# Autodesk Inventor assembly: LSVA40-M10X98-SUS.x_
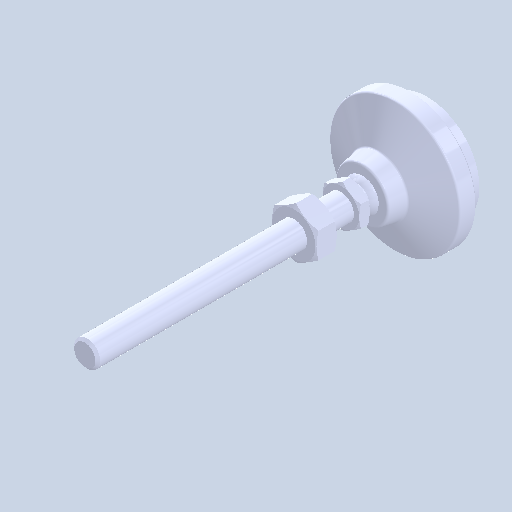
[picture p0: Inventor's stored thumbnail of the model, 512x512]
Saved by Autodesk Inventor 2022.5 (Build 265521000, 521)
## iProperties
Created: 2024-08
Part Number: LSVA40-M10X98-SUS.x_
Document SubType Name: Assembly
Designer: ImaoCorp
Author: ImaoCorp
Sending System: SOLIDWORKS 2022-2022290
MC: AMD64
MC_MODEL: Intel64 Family 6 Model 60 Stepping 3, GenuineIntel
OS: Windows_NT
FRU: Parasolid Version 33.1, build 260,  4-25-2022
FORMAT: text
GUISE: transmit
KEY: FILELSVA40-M10X98-SUS.x_t
DATE: Fri Aug 23 16:07:23 2024
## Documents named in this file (4)
- X:\14_SW2022-Inv2022\06_2024-10新製品(SME)\ELS_データ\l\lsva40-m10x98-sus\LSVA40-M10X98-SUS.x_.iam
- X:\14_SW2022-Inv2022\06_2024-10新製品(SME)\ELS_データ\l\lsva40-m10x98-sus\LSVA40-M10X98-SUS_01.ipt
- X:\14_SW2022-Inv2022\06_2024-10新製品(SME)\ELS_データ\l\lsva40-m10x98-sus\LSVA40-M10X98-SUS_02.ipt
- X:\14_SW2022-Inv2022\06_2024-10新製品(SME)\ELS_データ\l\lsva40-m10x98-sus\LSVA40-M10X98-SUS_03.ipt
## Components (3 placed, 3 different names)
1. LSVA40-M10X98-SUS_01
2. LSVA40-M10X98-SUS_02
3. LSVA40-M10X98-SUS_03
